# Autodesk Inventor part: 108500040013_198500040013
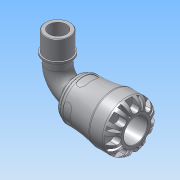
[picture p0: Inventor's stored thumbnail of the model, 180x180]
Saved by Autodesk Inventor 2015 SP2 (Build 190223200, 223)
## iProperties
Created: 2016-12
Part Number: 108500040013_198500040013
Material: PVC-Piping
Description: PLASSON 90° ELBOW WITH THREADED MALE OFFTAKE 40X1.1/4" SERIES 1
Document SubType Name: Modeling
Designer: KIM
Mass: 664.223 g
Surface Area: 733.008 cm^2
Volume: 474.445 cm^3
Density: 1.4 g/cm^3
Appearance: Smooth - White
Author: KIM
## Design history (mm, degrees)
derived "1085.ipt"
feature "Solid1::1085.ipt"
tag "TaggingFeature1"
body "Solid1"
other parameters: "d1" = 29.82, "d8" = 59.5, "d13" = 8, "d14" = 8, "d15" = 0, "d17" = 360 deg, "d19" = 8 deg, "d20" = 0.8, "d21" = 0.8, "d22" = 8 deg, "d24" = 0, "d26" = 360 deg, "d33" = 7, "d43" = 54.6, "d51" = 0.7, "d54" = 14, "d55" = 8.8, "d57" = 15.68, "d58" = 0, "d74" = 0, "d78" = 71, "d82" = 0.8, "d115" = 360 deg, "d207" = 90 deg, "d228" = 11.9, "d247" = 1.4, "d248" = 4.26, "d268" = 32.725, "d269" = 4.26, "d270" = 107, "d276" = 41.91, "d277" = 21, "d278" = 46.101, "d279" = 58, "d280" = 23.1, "d281" = 6.2865, "d283" = 37.719, "d286" = 0, "d287" = 0, "d288" = 29.337, "d290" = 8.4405, "d292" = 30 deg, "l_" = 71, "A_" = 107, "A_1" = 58, "l_2" = 21, "R_" = 41.91, "d9" = 10, "d289" = 29.337
